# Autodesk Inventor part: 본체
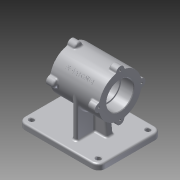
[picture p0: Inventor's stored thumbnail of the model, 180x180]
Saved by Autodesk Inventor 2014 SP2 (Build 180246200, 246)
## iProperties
Created: 2015-12
Part Number: 본체
Material: 알루미늄 6061
Document SubType Name: Modeling
Designer: Administrator
Density: 2.71 g/cm^3
Appearance: 알루미늄 - 평지
Mass: 1164.58 g
Surface Area: 814.942 cm^2
Volume: 429.733 cm^3
Author: Administrator
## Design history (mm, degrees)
sketch "스케치1"
  geometry: L1 (-70, 55)-(70, 55); L2 (70, 55)-(70, -55); L3 (70, -55)-(-70, -55); L4 (-70, -55)-(-70, 55); 3 further points
  constraints: 8 end point, 2 midpoint, 2 parallel, 1 horizontal, 1 horizontal alignment, 1 perpendicular, 1 vertical alignment
  dimensions: "d0" = 140 distance of L1.start L1.end; "d1" = 110 distance of L3.end L1.start
extrude "돌출1" new body sketch "스케치1" distance "d2" = 10; taper "d3" = 0 deg
node "작업 평면2"
  node "작업 평면1"
sketch "스케치2"
  geometry: L1 (70, -9.931)-(70, -82.976); L2 (-10, -55)-(85.359, -55); C1 r 37 at (70, -55)
  constraints: 4 end point, 2 point on line, 1 centre point, 1 perpendicular, 1 vertical
  dimensions: "d5" = 80 distance from line of L2.start L1; "d6" = 74 diameter of C1
extrude "돌출2" join sketch "스케치2" stored distance "d7" = 85; taper "d8" = 0 deg
sketch "스케치3"
  geometry: L1 (70, -55)-(-10, -55); L2 (0, -110)-(0, 0) reference; L3 (70, -92)-(-6.296, -92); L4 (70, -18)-(-6.296, -18); L5 (70, -18)-(70, -92); L6 (-6.296, -92)-(-6.296, -18); A1 r 37 centre (70, -55) between (70, -92) and (70, -18) reference
  constraints: 10 end point, 2 perpendicular, 2 point on circle, 2 symmetric about line, 1 horizontal, 1 parallel, 1 point on line
  dimensions: "d10" = 37 distance between parallel lines of L1 L3
extrude "돌출3" join sketch "스케치3" stored distance "d11" = 8; taper "d12" = 0 deg
sketch "스케치4"
  geometry: L1 (35, 50.324)-(35, 4.64); L2 (6, 10)-(14, 10) reference; L3 (10, 10)-(10, 60.476); L4 (70, 10)-(-70, 10) reference; L5 (35, 10)-(30.049, 50.324); L6 (35, 10)-(75.627, 10); L7 (-15, 10)-(-10.049, 50.324); L8 (-10.049, 50.324)-(30.049, 50.324); L9 (35, 10)-(-15, 10); 1 further point
  constraints: 14 end point, 2 parallel, 2 point on line, 2 symmetric about line, 1 equal length, 1 horizontal, 1 midpoint, 1 perpendicular, 1 vertical
  dimensions: "d13" = 25 distance between parallel lines of L1 L3; "d14" = 97 deg angle of L6 L5
extrude "돌출4" join sketch "스케치4" stored distance "d15" = 12; taper "d16" = 0 deg
sketch "스케치5"
  geometry: C1 r 37 at (0, 0) reference; C2 r 23.5 at (0, 0); 1 further point
  constraints: 1 centre point, 1 coincident
  dimensions: "d17" = 47 diameter of C2
extrude "돌출5" cut sketch "스케치5" distance "d18" = 22; taper "d19" = 0 deg
sketch "스케치6"
  geometry: C1 r 23.5 at (0, 0) reference; C2 r 21 at (0, 0); 1 further point
  constraints: 1 centre point, 1 coincident
  dimensions: "d20" = 42 diameter of C2
extrude "돌출6" cut sketch "스케치6" distance "d21" = 41; taper "d22" = 0 deg
sketch "스케치7"
  geometry: C1 r 37 at (0, 0) reference; C2 r 23.5 at (0, 0); 1 further point
  constraints: 1 centre point, 1 coincident
  dimensions: "d23" = 47 diameter of C2
extrude "돌출7" cut sketch "스케치7" distance "d24" = 22; taper "d25" = 0 deg
node "작업 평면3"
sketch "스케치9"
  geometry: L1 (70, 55)-(-70, 55) reference; L2 (-70, 55)-(-70, -55) reference; L3 (6, -37)-(6, -6) reference; L4 (0, 0)-(0, 16.938); L5 (0, 0)-(-28.163, 0); C1 r 4 at (-58, 43); C2 r 4 at (58, 43); C3 r 4 at (-58, -43); C4 r 4 at (58, -43)
  constraints: 4 centre point, 4 end point, 3 symmetric about line, 1 parallel, 1 perpendicular, 3 other
  dimensions: "d32" = 8 diameter of C1; "d33" = 12 distance from line of L1 C1.centre; "d34" = 12 distance from line of L2 C1.centre
extrude "돌출9" cut sketch "스케치9" distance "d35" = 15; taper "d36" = 0 deg
node "작업 평면4"
sketch "스케치10"
  geometry: L1 (37, 70)-(10.837, 96.163); L2 (37, 70)-(74, 70); C1 r 21 at (37, 70) reference; 1 further point
  constraints: 4 end point, 1 equal length, 1 horizontal
  dimensions: "d37" = 37 distance of L1.start L1.end; "d38" = 135 deg angle of L2 L1
node "작업 평면5"
sketch "스케치11"
  geometry: L1 (25.377, -5.139)-(-25.377, -5.139); L2 (-25.377, -5.139)-(-25.377, 10.054); L3 (-25.377, 10.054)-(25.377, 10.054); L4 (25.377, 10.054)-(25.377, -5.139); L5 (0, -5.139)-(0, 10.054); L6 (42.5, -26.163)-(42.5, -26.163) reference; 1 further point
  constraints: 2 end point, 2 midpoint, 2 other
  dimensions: "d39" = 42.5 distance between parallel lines of L6 L5
feature "엠보싱1" sketch "스케치11" dims "d0" = 140, "d1" = 110, "d40" = 0.5, "d41" = 0
fillet "모깎기1" dims "d56" = 0.3, "d57" = 3, "d58" = 12
chamfer "모따기1" distance "d59" = 1; stored, may be unused: second distance "d60" = 2, angle "d61" = 45 deg
fillet "모깎기2" dims "d62" = 3
sketch "스케치14"
  geometry: L1 (-32.5, 117)-(52.5, 117) reference; L2 (-17.5, 115.281)-(-17.5, 117); L3 (-32.5, 117)-(-32.5, 117) reference; L4 (-17.5, 117)-(-20.048, 124); L5 (-17.5, 117)-(-1.549, 117); L6 (-32.5, 124)-(-20.048, 124); L7 (-32.5, 117)-(-32.5, 124); L8 (-17.5, 117)-(-32.5, 117); 1 further point
  constraints: 12 end point, 2 perpendicular, 1 horizontal, 1 parallel, 1 point on line
  dimensions: "d63" = 15 distance between parallel lines of L3 L2; "d64" = 110 deg angle of L5 L4; "d65" = 7 distance between parallel lines of L1 L6
revolve "회전1" sketch "스케치14" stored, may be unused: angle "d66" = 90 deg
node "작업 평면7"
  node "작업 평면6"
sketch "스케치15"
  geometry: A1 r 7 centre (55, 107) between (61.969, 106.338) and (48.031, 106.338) reference; A2 r 7 centre (18, 70) between (18.662, 76.969) and (18.662, 63.031) reference; A3 r 7 centre (55, 33) between (48.031, 33.662) and (61.969, 33.662) reference; A4 r 7 centre (92, 70) between (91.338, 63.031) and (91.338, 76.969) reference; 5 further points
  constraints: 4 coincident
hole "구멍3" sketch "스케치15" at (55, 107), (92, 70), (55, 33), (18, 70) diameter "d72" = 3.242; stored, may be unused: countersink angle "d76" = 90 deg, drill point angle "d78" = 118 deg; dims "d73" = 9, "d74" = 4, "d75" = 2, "d77" = 11
sketch "스케치16"
  geometry: A1 r 7 centre (-55, 33) between (-61.969, 33.662) and (-48.031, 33.662) reference; A2 r 7 centre (-18, 70) between (-18.662, 63.031) and (-18.662, 76.969) reference; A3 r 7 centre (-55, 107) between (-48.031, 106.338) and (-61.969, 106.338) reference; A4 r 7 centre (-92, 70) between (-91.338, 76.969) and (-91.338, 63.031) reference; 5 further points
  constraints: 4 coincident
hole "구멍4" sketch "스케치16" at (-55, 107), (-18, 70), (-55, 33), (-92, 70) diameter "d79" = 3.242; stored, may be unused: countersink angle "d83" = 90 deg, drill point angle "d85" = 118 deg; dims "d80" = 9, "d81" = 4, "d82" = 2, "d84" = 11
fillet "모깎기3" dims "d86" = 3
node "솔리드1"
pattern_circular "원형 패턴1" dims angle "d68" = 360 deg
mirror "대칭2"
